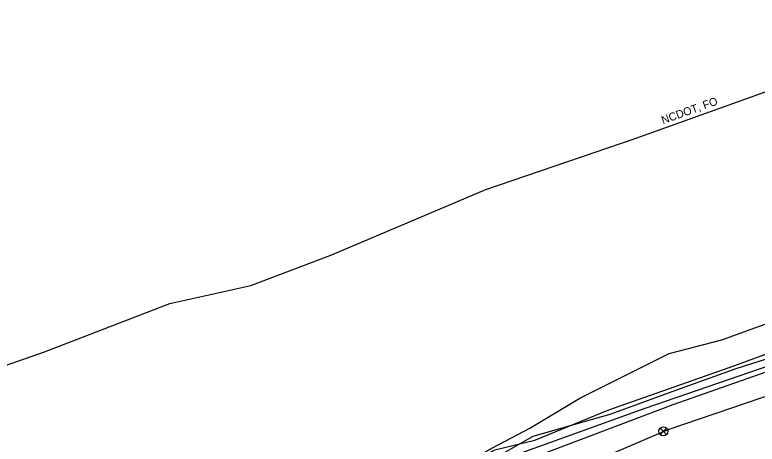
# Model space of a CAD drawing. Extents: x 2070721 to 2083039, y 729290 to 737883.
# Drawn here: x 2080173.8 to 2080544.7, y 734542.4 to 734756.8 of the extents above; entities that cross this region are included whole.
import ezdxf

# ---------------------------------------------------------------- set-up
doc = ezdxf.new("R2010")
doc.units = 0
for name, color, linetype in [('COGO Default Point Elevation', 7, 'Continuous'), ('Exist Utilities Gas UG Line SUE LOS B Cogo Comment', 7, 'Continuous'), ('Exist Utilities Power Pole CELL', 7, 'Continuous'), ('Exist Utilities TV Pedestal Cogo Elevation', 7, 'Continuous'), ('Exist Utilities TV UG Cable Cogo Point CELL', 7, 'Continuous'), ('Exist Utilities TV UG Cable SUE LOS C Cogo Point CELL', 7, 'Continuous')]:
    doc.layers.add(name, color=color, linetype=linetype)

msp = doc.modelspace()

# ---------------------------------------------------------------- linework, layer by layer
at = {"layer": 'COGO Default Point Elevation'}
msp.add_lwpolyline([(2080499.42, 734550.41), (2080496.27, 734547.26), (2080497.84, 734548.83), (2080499.42, 734547.26), (2080496.27, 734550.41)], dxfattribs=at)
msp.add_circle((2080497.84, 734548.83), 2.23, dxfattribs=at)
at = {"layer": 'Exist Utilities Power Pole CELL'}
msp.add_lwpolyline([(2080232.24, 734245.67), (2080237.5, 734254.36), (2080238.66, 734282.35), (2080245.75, 734323.83), (2080258.86, 734369.55), (2080269.86, 734398.57), (2080309.08, 734449.32), (2080323.63, 734464.88), (2080355.41, 734492.16), (2080379.52, 734509.8), (2080416.03, 734529.49), (2080502.71, 734562.3), (2080573.96, 734587.12), (2080616.57, 734603.22), (2080677.16, 734624.99), (2080749, 734651.22), (2080815.57, 734674.3), (2080861.11, 734690.56), (2080923.26, 734714.15), (2080934.26, 734720.97)], dxfattribs=at)
at = {"layer": 'Exist Utilities TV Pedestal Cogo Elevation'}
msp.add_lwpolyline([(2080357.06, 734003.27), (2080353.32, 734006.79), (2080296.63, 734072.2), (2080261.95, 734141.13), (2080251.22, 734185.42), (2080250, 734189.2), (2080244.12, 734248.6), (2080244.13, 734251.5), (2080244.63, 734259.68), (2080245.13, 734264.1), (2080254.44, 734320.44), (2080276.53, 734380.91), (2080391.41, 734503.18), (2080497.9, 734548.7), (2080500.72, 734549.83), (2080585.45, 734578.7), (2080702.53, 734619.89), (2080710.17, 734622.62), (2080743.51, 734634.52), (2080754.26, 734638.28), (2080902.52, 734692.58), (2081024.44, 734735.33)], dxfattribs=at)
at = {"layer": 'Exist Utilities TV UG Cable Cogo Point CELL'}
for points in [[(2080527.18, 734594.58), (2080756.63, 734677.7), (2080975.53, 734755.33), (2081114.85, 734806.49), (2081251.31, 734880.3), (2081357.91, 734934.96), (2081407.46, 734955.63), (2081557.34, 735013.56), (2081611.19, 735031.21), (2081670.8, 735036.79), (2081727.82, 735033.26), (2081796.62, 735020.83), (2081876.61, 734998.57), (2081913.61, 734982.12), (2081940.08, 734960.79), (2081955.36, 734908.6), (2081940.34, 734844.38), (2081917.15, 734795.51)], [(2080392.43, 734459.45), (2080392.18, 734455.98), (2080369.79, 734491.21), (2080371.64, 734506.16), (2080398.8, 734522.93), (2080423.1, 734536.76), (2080488.87, 734560.43), (2080551.19, 734581.93), (2080605.97, 734600.8), (2080683.17, 734629.37), (2080713.38, 734633.09), (2080745.42, 734609.78), (2080760.77, 734576.63), (2080781.91, 734561.06), (2080789.84, 734547.84), (2080795.45, 734523.96), (2080798.47, 734502.81), (2080795.45, 734476.11), (2080787.39, 734456.13)], [(2080389.44, 734455.05), (2080371.58, 734477.3), (2080359.8, 734497.02), (2080353.64, 734504.17), (2080362.14, 734509.13), (2080380.41, 734522.38), (2080412.54, 734540.56), (2080431.18, 734550.33), (2080456.15, 734565.37), (2080500.74, 734587.65), (2080527.18, 734594.58)]]:
    msp.add_lwpolyline(points, dxfattribs=at)
at = {"layer": 'Exist Utilities TV UG Cable SUE LOS C Cogo Point CELL'}
for points in [[(2079745.48, 734481.51), (2079801.23, 734497.35), (2079872.83, 734508.05), (2079949.65, 734523.37), (2080020.61, 734534.5), (2080089.55, 734553.89), (2080188.62, 734588.57), (2080251.31, 734612.62), (2080291.78, 734621.68), (2080331.66, 734636.74), (2080409.13, 734669.6), (2080483.75, 734695.04), (2080565.61, 734724.43), (2080648.3, 734753.97), (2080723.36, 734781.19), (2080819.84, 734816.74), (2080898.17, 734842.61), (2080939.09, 734839.81)], [(2080235.11, 734249.36), (2080234.94, 734252.48), (2080236.58, 734281.87), (2080244.62, 734323.58), (2080257.8, 734369.84), (2080268.59, 734399.28), (2080285.42, 734425.78), (2080306.49, 734446.52), (2080318.99, 734464.89), (2080332.07, 734479.26), (2080365.28, 734504.24), (2080415, 734536.31), (2080432.75, 734546.34), (2080471.85, 734557.5), (2080502.31, 734568.65), (2080534.18, 734580.2), (2080570.94, 734591.77), (2080576.66, 734593.81), (2080717.24, 734648.01)], [(2080228.28, 734243.43), (2080230.55, 734282.39), (2080237.1, 734324.84), (2080265.61, 734400.42), (2080300.19, 734451.55), (2080329.83, 734482.91), (2080380.99, 734522.11), (2080413.6, 734539.64), (2080433.63, 734544.47), (2080470.56, 734559.5), (2080533.58, 734581.77), (2080652.68, 734625.4)]]:
    msp.add_lwpolyline(points, dxfattribs=at)

# ---------------------------------------------------------------- texts
at = {"layer": 'Exist Utilities Gas UG Line SUE LOS B Cogo Comment'}
msp.add_text('NCDOT, FO', height=4, rotation=19.7495, dxfattribs=at).set_placement((2080497.71, 734702.18))

doc.saveas('drawing.dxf')
